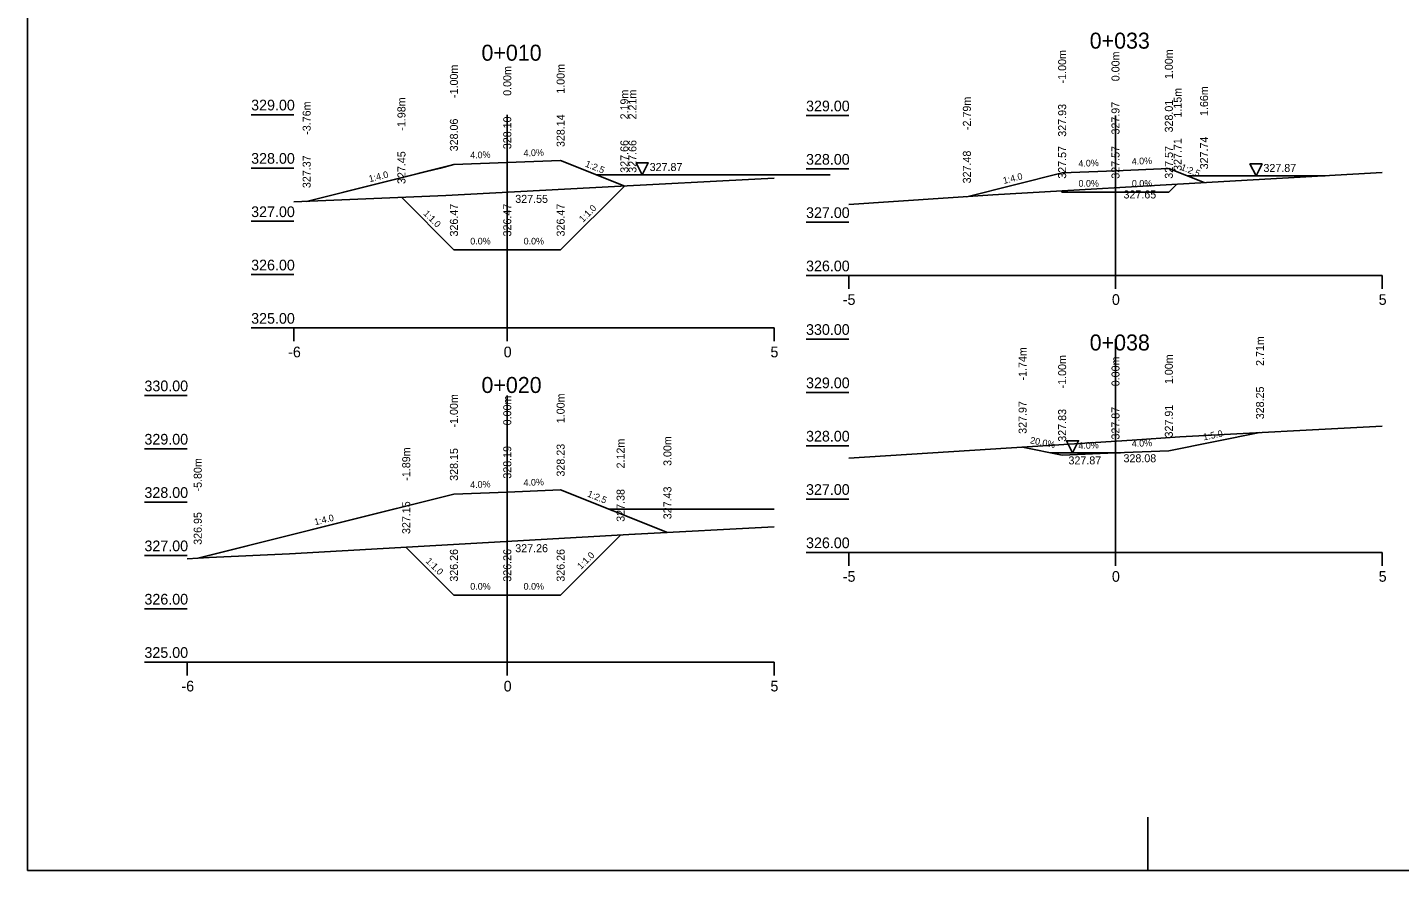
# Model space of a CAD drawing. Extents: x -560209.6 to -560167.6, y -1162747.5 to -1162717.8.
# Drawn here: x -560209.56 to -560183.84, y -1162747.49 to -1162731.68 of the extents above; entities that cross this region are included whole.
import ezdxf

# ---------------------------------------------------------------- set-up
doc = ezdxf.new("R2010")
doc.units = 0
for name, color, linetype in [('16', 7, 'Continuous'), ('21', 7, 'Continuous'), ('28', 7, 'Continuous'), ('59', 7, 'Continuous'), ('Body pricny rez', 7, 'Continuous'), ('Popis pricneho profilu', 7, 'Continuous')]:
    doc.layers.add(name, color=color, linetype=linetype)

msp = doc.modelspace()

# ---------------------------------------------------------------- linework, layer by layer
for p, q in [((-560209.561, -1162717.787), (-560209.561, -1162747.487)), ((-560188.561, -1162747.487), (-560188.561, -1162746.487)), ((-560209.561, -1162747.487), (-560167.561, -1162747.487))]:
    msp.add_line(p, q)
for points in [[(-560204.328, -1162734.939), (-560203.182, -1162734.652), (-560202.084, -1162734.378), (-560201.82, -1162734.312), (-560201.568, -1162734.249), (-560200.568, -1162734.209), (-560199.568, -1162734.169), (-560198.362, -1162734.651)], [(-560201.568, -1162734.249), (-560204.328, -1162734.939)], [(-560200.568, -1162734.209), (-560201.568, -1162734.249)], [(-560200.568, -1162734.209), (-560199.568, -1162734.169)], [(-560199.568, -1162734.169), (-560198.362, -1162734.651)], [(-560204.568, -1162734.949), (-560201.719, -1162734.826), (-560198.56, -1162734.661), (-560195.928, -1162734.52), (-560195.568, -1162734.5)], [(-560198.885, -1162734.442), (-560194.514, -1162734.442)], [(-560194.168, -1162734.999), (-560191.467, -1162734.817), (-560187.138, -1162734.565), (-560184.168, -1162734.399)], [(-560190.168, -1162734.403), (-560191.954, -1162734.85)], [(-560189.168, -1162734.363), (-560190.168, -1162734.403)], [(-560189.168, -1162734.363), (-560188.168, -1162734.323)], [(-560188.168, -1162734.323), (-560187.508, -1162734.587)], [(-560187.827, -1162734.459), (-560185.241, -1162734.459)], [(-560202.551, -1162734.862), (-560201.568, -1162735.846), (-560200.568, -1162735.846), (-560199.568, -1162735.846), (-560198.373, -1162734.651)], [(-560199.568, -1162735.846), (-560198.373, -1162734.651)], [(-560190.188, -1162734.742), (-560190.168, -1162734.763), (-560189.276, -1162734.763), (-560189.168, -1162734.763), (-560188.276, -1162734.763), (-560188.168, -1162734.763), (-560188.132, -1162734.727), (-560188.021, -1162734.617)], [(-560189.168, -1162734.763), (-560190.168, -1162734.763)], [(-560189.168, -1162734.763), (-560188.168, -1162734.763)], [(-560188.168, -1162734.763), (-560188.021, -1162734.617)], [(-560201.568, -1162735.846), (-560202.551, -1162734.862)], [(-560200.568, -1162735.846), (-560201.568, -1162735.846)], [(-560200.568, -1162735.846), (-560199.568, -1162735.846)], [(-560194.168, -1162739.754), (-560188.854, -1162739.417), (-560187.965, -1162739.353), (-560184.168, -1162739.153)], [(-560188.168, -1162739.615), (-560186.46, -1162739.274)], [(-560190.168, -1162739.695), (-560190.909, -1162739.547)], [(-560190.387, -1162739.651), (-560189.073, -1162739.651)], [(-560189.168, -1162739.655), (-560190.168, -1162739.695)], [(-560189.168, -1162739.655), (-560188.168, -1162739.615)], [(-560206.369, -1162741.628), (-560206.111, -1162741.564), (-560205.985, -1162741.532), (-560203.7, -1162740.961), (-560201.568, -1162740.428), (-560200.568, -1162740.388), (-560199.568, -1162740.348), (-560197.566, -1162741.149)], [(-560201.568, -1162740.428), (-560206.369, -1162741.628)], [(-560200.568, -1162740.388), (-560201.568, -1162740.428)], [(-560200.568, -1162740.388), (-560199.568, -1162740.348)], [(-560199.568, -1162740.348), (-560197.566, -1162741.149)], [(-560198.667, -1162740.708), (-560195.568, -1162740.708)], [(-560206.568, -1162741.639), (-560206.154, -1162741.617), (-560204.647, -1162741.55), (-560198.18, -1162741.181), (-560198.173, -1162741.181), (-560195.568, -1162741.042)], [(-560202.462, -1162741.426), (-560201.568, -1162742.32), (-560200.568, -1162742.32), (-560199.568, -1162742.32), (-560198.444, -1162741.196)], [(-560199.568, -1162742.32), (-560198.444, -1162741.196)], [(-560201.568, -1162742.32), (-560202.462, -1162741.426)], [(-560200.568, -1162742.32), (-560201.568, -1162742.32)], [(-560200.568, -1162742.32), (-560199.568, -1162742.32)]]:
    msp.add_lwpolyline(points)
for points in [[(-560198.039, -1162734.442), (-560198.151, -1162734.217), (-560197.926, -1162734.217)], [(-560186.534, -1162734.459), (-560186.647, -1162734.234), (-560186.422, -1162734.234)], [(-560189.971, -1162739.651), (-560190.084, -1162739.426), (-560189.859, -1162739.426)]]:
    msp.add_lwpolyline(points, close=True)
at = {"layer": '16'}
for p, q in [((-560194.168, -1162736.329), (-560184.168, -1162736.329)), ((-560204.568, -1162737.312), (-560195.568, -1162737.312)), ((-560194.168, -1162741.521), (-560184.168, -1162741.521)), ((-560206.568, -1162743.578), (-560195.568, -1162743.578))]:
    msp.add_line(p, q, dxfattribs=at)
at = {"layer": '21'}
for p, q in [((-560205.368, -1162733.312), (-560204.568, -1162733.312)), ((-560194.968, -1162733.329), (-560194.168, -1162733.329)), ((-560205.368, -1162734.312), (-560204.568, -1162734.312)), ((-560194.968, -1162734.329), (-560194.168, -1162734.329)), ((-560205.368, -1162735.312), (-560204.568, -1162735.312)), ((-560194.968, -1162735.329), (-560194.168, -1162735.329)), ((-560205.368, -1162736.312), (-560204.568, -1162736.312)), ((-560194.968, -1162736.329), (-560194.168, -1162736.329)), ((-560205.368, -1162737.312), (-560204.568, -1162737.312)), ((-560194.968, -1162737.521), (-560194.168, -1162737.521)), ((-560207.368, -1162738.578), (-560206.568, -1162738.578)), ((-560194.968, -1162738.521), (-560194.168, -1162738.521)), ((-560207.368, -1162739.578), (-560206.568, -1162739.578)), ((-560194.968, -1162739.521), (-560194.168, -1162739.521)), ((-560207.368, -1162740.578), (-560206.568, -1162740.578)), ((-560194.968, -1162740.521), (-560194.168, -1162740.521)), ((-560207.368, -1162741.578), (-560206.568, -1162741.578)), ((-560194.968, -1162741.521), (-560194.168, -1162741.521)), ((-560207.368, -1162742.578), (-560206.568, -1162742.578)), ((-560207.368, -1162743.578), (-560206.568, -1162743.578))]:
    msp.add_line(p, q, dxfattribs=at)
at = {"layer": '28'}
for p, q in [((-560200.568, -1162733.312), (-560200.568, -1162737.312)), ((-560189.168, -1162733.329), (-560189.168, -1162736.329)), ((-560189.168, -1162737.521), (-560189.168, -1162741.521)), ((-560200.568, -1162738.578), (-560200.568, -1162743.578))]:
    msp.add_line(p, q, dxfattribs=at)
at = {"layer": '59'}
for p, q in [((-560194.168, -1162736.579), (-560194.168, -1162736.329)), ((-560189.168, -1162736.579), (-560189.168, -1162736.329)), ((-560184.168, -1162736.579), (-560184.168, -1162736.329)), ((-560204.568, -1162737.562), (-560204.568, -1162737.312)), ((-560200.568, -1162737.562), (-560200.568, -1162737.312)), ((-560195.568, -1162737.562), (-560195.568, -1162737.312)), ((-560194.168, -1162741.771), (-560194.168, -1162741.521)), ((-560189.168, -1162741.771), (-560189.168, -1162741.521)), ((-560184.168, -1162741.771), (-560184.168, -1162741.521)), ((-560206.568, -1162743.828), (-560206.568, -1162743.578)), ((-560200.568, -1162743.828), (-560200.568, -1162743.578)), ((-560195.568, -1162743.828), (-560195.568, -1162743.578))]:
    msp.add_line(p, q, dxfattribs=at)

# ---------------------------------------------------------------- texts
for s, height, p in [('0+033', 0.3, (-560189.651, -1162732.074)), ('0+010', 0.3, (-560201.051, -1162732.3)), ('327.87', 0.15, (-560197.899, -1162734.369)), ('327.87', 0.15, (-560186.395, -1162734.386)), ('0+038', 0.3, (-560189.651, -1162737.734)), ('0+020', 0.3, (-560201.051, -1162738.531)), ('327.87', 0.15, (-560190.049, -1162739.87))]:
    msp.add_text(s, height=height).set_placement(p)
for s, rotation, p in [('1:2.5', 338.1986, (-560199.119, -1162734.281)), ('1:2.5', 338.1986, (-560187.956, -1162734.345)), ('1:4.0', 14.0362, (-560203.147, -1162734.579)), ('1:4.0', 14.0362, (-560191.26, -1162734.612)), ('1:1.0', 45, (-560199.149, -1162735.339)), ('1:1.0', 315, (-560202.15, -1162735.176)), ('1:5.0', 11.3099, (-560187.513, -1162739.42)), ('1:2.5', 338.1986, (-560199.078, -1162740.47)), ('1:4.0', 14.0362, (-560204.168, -1162741.014)), ('1:1.0', 315, (-560202.105, -1162741.694)), ('1:1.0', 45, (-560199.184, -1162741.848))]:
    msp.add_text(s, height=0.125, rotation=rotation).set_placement(p)
at = {"layer": '16'}
for s, rotation, p in [('4.0%', 2.2906, (-560201.261, -1162734.136)), ('4.0%', 2.2906, (-560200.261, -1162734.096)), ('4.0%', 2.2906, (-560189.861, -1162734.291)), ('4.0%', 2.2906, (-560188.861, -1162734.251)), ('0.0%', 0, (-560188.861, -1162734.663)), ('20.0%', 348.6901, (-560190.776, -1162739.474)), ('4.0%', 2.2906, (-560188.861, -1162739.543)), ('4.0%', 2.2906, (-560189.861, -1162739.583)), ('4.0%', 2.2906, (-560201.261, -1162740.316)), ('4.0%', 2.2906, (-560200.261, -1162740.276))]:
    msp.add_text(s, height=0.125, rotation=rotation, dxfattribs=at).set_placement(p)
for p in [(-560189.861, -1162734.663), (-560201.261, -1162735.746), (-560200.261, -1162735.746), (-560201.261, -1162742.22), (-560200.261, -1162742.22)]:
    msp.add_text('0.0%', height=0.125, dxfattribs=at).set_placement(p)
at = {"layer": '21'}
for s, p in [('329.00', (-560205.368, -1162733.232)), ('329.00', (-560194.968, -1162733.249)), ('328.00', (-560205.368, -1162734.232)), ('328.00', (-560194.968, -1162734.249)), ('327.00', (-560205.368, -1162735.232)), ('327.00', (-560194.968, -1162735.249)), ('326.00', (-560205.368, -1162736.232)), ('326.00', (-560194.968, -1162736.249)), ('-5', (-560194.279, -1162736.879)), ('0', (-560189.235, -1162736.879)), ('5', (-560184.235, -1162736.879)), ('325.00', (-560205.368, -1162737.232)), ('330.00', (-560194.968, -1162737.441)), ('-6', (-560204.675, -1162737.862)), ('0', (-560200.635, -1162737.862)), ('5', (-560195.635, -1162737.862)), ('330.00', (-560207.368, -1162738.498)), ('329.00', (-560194.968, -1162738.441)), ('329.00', (-560207.368, -1162739.498)), ('328.00', (-560194.968, -1162739.441)), ('328.00', (-560207.368, -1162740.498)), ('327.00', (-560194.968, -1162740.441)), ('327.00', (-560207.368, -1162741.498)), ('326.00', (-560194.968, -1162741.441)), ('-5', (-560194.279, -1162742.071)), ('0', (-560189.235, -1162742.071)), ('5', (-560184.235, -1162742.071)), ('326.00', (-560207.368, -1162742.498)), ('325.00', (-560207.368, -1162743.498)), ('-6', (-560206.675, -1162744.128)), ('0', (-560200.635, -1162744.128)), ('5', (-560195.635, -1162744.128))]:
    msp.add_text(s, height=0.2, dxfattribs=at).set_placement(p)
at = {"layer": '59'}
for s, p in [('327.65', (-560189.018, -1162734.883)), ('327.55', (-560200.418, -1162734.966)), ('328.08', (-560189.018, -1162739.83)), ('327.26', (-560200.418, -1162741.517))]:
    msp.add_text(s, height=0.15, dxfattribs=at).set_placement(p)
at = {"layer": 'Body pricny rez'}
for p in [(-560201.568, -1162734.249), (-560200.568, -1162734.209), (-560199.568, -1162734.169), (-560190.168, -1162734.404), (-560189.168, -1162734.364), (-560188.168, -1162734.324), (-560198.373, -1162734.652), (-560198.363, -1162734.651), (-560190.168, -1162734.764), (-560189.168, -1162734.764), (-560188.168, -1162734.764), (-560188.022, -1162734.617), (-560187.509, -1162734.587), (-560204.329, -1162734.939), (-560202.552, -1162734.863), (-560191.955, -1162734.85), (-560201.568, -1162735.847), (-560200.568, -1162735.847), (-560199.568, -1162735.847), (-560186.461, -1162739.274), (-560190.909, -1162739.547), (-560189.168, -1162739.656), (-560188.168, -1162739.616), (-560190.168, -1162739.696), (-560201.568, -1162740.429), (-560200.568, -1162740.389), (-560199.568, -1162740.349), (-560198.444, -1162741.197), (-560197.567, -1162741.149), (-560202.463, -1162741.426), (-560206.369, -1162741.629), (-560201.568, -1162742.32), (-560200.568, -1162742.32), (-560199.568, -1162742.32)]:
    msp.add_text('+', height=0.001, dxfattribs=at).set_placement(p)
at = {"layer": 'Popis pricneho profilu'}
for s, p in [('-1.00m', (-560190.093, -1162732.725)), ('0.00m', (-560189.093, -1162732.685)), ('1.00m', (-560188.093, -1162732.645)), ('-1.00m', (-560201.493, -1162732.999)), ('0.00m', (-560200.493, -1162732.959)), ('1.00m', (-560199.493, -1162732.919)), ('-1.98m', (-560202.476, -1162733.612)), ('2.19m', (-560198.298, -1162733.401)), ('2.21m', (-560198.147, -1162733.401)), ('-2.79m', (-560191.879, -1162733.6)), ('1.15m', (-560187.928, -1162733.367)), ('1.66m', (-560187.433, -1162733.337)), ('-3.76m', (-560204.253, -1162733.689)), ('327.93', (-560190.093, -1162733.725)), ('327.97', (-560189.093, -1162733.685)), ('328.01', (-560188.093, -1162733.645)), ('328.06', (-560201.493, -1162733.999)), ('328.10', (-560200.493, -1162733.959)), ('328.14', (-560199.493, -1162733.919)), ('327.71', (-560187.928, -1162734.367)), ('327.74', (-560187.433, -1162734.337)), ('327.45', (-560202.476, -1162734.612)), ('327.66', (-560198.298, -1162734.401)), ('327.66', (-560198.147, -1162734.401)), ('327.48', (-560191.879, -1162734.6)), ('327.57', (-560190.093, -1162734.513)), ('327.57', (-560189.093, -1162734.513)), ('327.57', (-560188.093, -1162734.513)), ('327.37', (-560204.253, -1162734.689)), ('326.47', (-560201.493, -1162735.596)), ('326.47', (-560200.493, -1162735.596)), ('326.47', (-560199.493, -1162735.596)), ('2.71m', (-560186.385, -1162738.024)), ('-1.74m', (-560190.834, -1162738.297)), ('-1.00m', (-560190.093, -1162738.445)), ('0.00m', (-560189.093, -1162738.405)), ('1.00m', (-560188.093, -1162738.365)), ('-1.00m', (-560201.493, -1162739.178)), ('0.00m', (-560200.493, -1162739.138)), ('1.00m', (-560199.493, -1162739.098)), ('328.25', (-560186.385, -1162739.024)), ('327.97', (-560190.834, -1162739.297)), ('327.83', (-560190.093, -1162739.445)), ('327.87', (-560189.093, -1162739.405)), ('327.91', (-560188.093, -1162739.365)), ('2.12m', (-560198.369, -1162739.946)), ('3.00m', (-560197.491, -1162739.899)), ('-1.89m', (-560202.387, -1162740.176)), ('328.15', (-560201.493, -1162740.178)), ('328.19', (-560200.493, -1162740.138)), ('328.23', (-560199.493, -1162740.098)), ('-5.80m', (-560206.294, -1162740.378)), ('327.38', (-560198.369, -1162740.946)), ('327.43', (-560197.491, -1162740.899)), ('327.15', (-560202.387, -1162741.176)), ('326.95', (-560206.294, -1162741.378)), ('326.26', (-560201.493, -1162742.07)), ('326.26', (-560200.493, -1162742.07)), ('326.26', (-560199.493, -1162742.07))]:
    msp.add_text(s, height=0.15, rotation=90, dxfattribs=at).set_placement(p)

doc.saveas('drawing.dxf')
